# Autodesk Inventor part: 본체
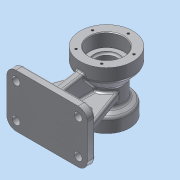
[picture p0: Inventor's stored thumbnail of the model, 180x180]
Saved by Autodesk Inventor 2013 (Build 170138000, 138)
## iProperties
Created: 2015-08
Part Number: 본체
Material: 알루미늄 6061
Document SubType Name: Modeling
Designer: dgall
Density: 2.71 g/cm^3
Mass: 1053.19 g
Surface Area: 752.18 cm^2
Volume: 388.632 cm^3
Author: dgall
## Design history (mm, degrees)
sketch "스케치1"
  geometry: L1 (0, 0)-(0, -80); L2 (0, -80)-(-122, -80); L3 (-122, -80)-(-122, 0); L4 (-122, 0)-(0, 0); L5 (-14, -66)-(-108, -66); L6 (-108, -66)-(-108, -14); L7 (-108, -14)-(-14, -14); L8 (-14, -14)-(-14, -66); C1 r 6 at (-14, -66); C2 r 6 at (-14, -14); C3 r 6 at (-108, -14); C4 r 6 at (-108, -66); 4 further points
  constraints: 16 end point, 4 centre point, 4 coincident, 4 midpoint, 4 parallel, 2 perpendicular, 1 horizontal, 1 horizontal alignment, 1 vertical, 1 vertical alignment
  dimensions: "d0" = 80 distance of L1.start L1.end; "d1" = 122 distance of L1.end L2.end; "d2" = 94 distance of L5.start L5.end; "d3" = 52 distance of L7.end L5.start; "d4" = 12 diameter of C1; "d5" = 12 diameter of C2; "d6" = 12 diameter of C3; "d7" = 12 diameter of C4
extrude "돌출1" new body sketch "스케치1" distance "d8" = 12; taper "d9" = 0 deg
node "작업 평면1"
sketch "스케치2"
  geometry: L1 (80, 12)-(80, 0) reference; L2 (80, 0)-(0, 0) reference; L3 (0, 0)-(0, 12) reference; L4 (0, 12)-(80, 12) reference; L5 (40, 0)-(40, 90); L6 (0, 90)-(90, 90); L7 (0, 90)-(0, 125); L8 (0, 125)-(20, 125); L9 (20, 125)-(25.774, 115); L10 (25.774, 115)-(52.124, 115); L11 (52.124, 115)-(70, 130); L12 (70, 130)-(90, 130); L13 (90, 130)-(90, 90)
  constraints: 18 end point, 5 perpendicular, 2 parallel, 1 midpoint, 1 vertical alignment
  dimensions: "d10" = 90 distance of L5.start L5.end; "d11" = 90 distance of L6.start L6.end; "d12" = 70 diameter of L8 L6; "d13" = 20 distance of L7.end L8.end; "d14" = 60 deg angle of L10 L9; "d15" = 20 distance of L11.end L12.end; "d16" = 40 deg angle of L10 L11; "d17" = 50 diameter of L10 L6; "d18" = 80 diameter of L12 L6; "d19" = 130 distance between parallel lines of L2 L12
revolve "회전1" sketch "스케치2" stored, may be unused: angle "d20" = 90 deg
sketch "스케치3"
  geometry: C1 r 35 at (0, 0) reference; C2 r 20 at (0, 0); 1 further point
  constraints: 1 centre point, 1 coincident
  dimensions: "d21" = 40 diameter of C2
extrude "돌출2" cut sketch "스케치3" distance "d22" = 17; taper "d23" = 0 deg
sketch "스케치4"
  geometry: C1 r 40 at (0, 0) reference; C2 r 26 at (0, 0); 1 further point
  constraints: 1 centre point, 1 coincident
  dimensions: "d24" = 52 diameter of C2
extrude "돌출3" cut sketch "스케치4" distance "d25" = 20; taper "d26" = 0 deg
sketch "스케치5"
  geometry: C1 r 26 at (0, 0) reference; C2 r 19 at (0, 0); 1 further point
  constraints: 1 centre point, 1 coincident
  dimensions: "d27" = 38 diameter of C2
extrude "돌출4" cut sketch "스케치5" distance "d28" = 3; taper "d29" = 0 deg
sketch "스케치6"
  geometry: C1 r 19 at (0, 0) reference; C2 r 16 at (0, 0); 1 further point
  constraints: 1 centre point, 1 coincident
  dimensions: "d30" = 32 diameter of C2
extrude "돌출5" cut sketch "스케치6" stored distance "d31" = 3; taper "d32" = 0 deg
sketch "스케치7" dims "d33" = 66
  geometry: C1 r 26 at (0, 0) reference; C2 r 40 at (0, 0) reference; 3 further points
  constraints: 2 vertical alignment, 1 coincident, 2 other
hole "구멍1" sketch "스케치7" at (0, 33) diameter "d34" = 3.459; stored, may be unused: countersink angle "d38" = 90 deg, drill point angle "d40" = 118 deg; dims "d35" = 10, "d36" = 4, "d37" = 2, "d39" = 13
sketch "스케치8" dims "d44" = 54
  geometry: C1 r 20 at (0, 0) reference; C2 r 35 at (0, 0) reference; 3 further points
  constraints: 2 vertical alignment, 1 coincident, 2 other
hole "구멍2" sketch "스케치8" at (0, 27) diameter "d45" = 3.459; stored, may be unused: countersink angle "d49" = 90 deg, drill point angle "d51" = 118 deg; dims "d46" = 10, "d47" = 4, "d48" = 2, "d50" = 13
node "작업 평면2"
sketch "스케치10"
  geometry: L1 (0, 0)-(0, 12) reference; L2 (0, 12)-(122, 12) reference; L3 (122, 12)-(122, 0) reference; L4 (122, 0)-(0, 0) reference; L5 (10, 12)-(36.529, 84.887); L6 (112, 12)-(85.471, 84.887); L7 (10, 12)-(112, 12); L8 (31, 36)-(31, 30); L9 (43, 36)-(43, 30); L10 (61, 90)-(61, 0); L11 (79, 36)-(79, 30); L12 (91, 36)-(91, 30); C1 r 16 at (61, 90) reference; A1 r 25 centre (61, 90) between (36.529, 84.887) and (85.471, 84.887); A2 r 6 centre (37, 30) between (31, 30) and (43, 30); A3 r 6 centre (37, 36) between (43, 36) and (31, 36); A4 r 6 centre (85, 36) between (91, 36) and (79, 36); A5 r 6 centre (85, 30) between (79, 30) and (91, 30); 1 further point
  constraints: 16 end point, 10 point on circle, 6 symmetric about line, 5 centre point, 4 tangent, 2 parallel, 1 coincident, 1 horizontal alignment, 1 midpoint, 1 perpendicular, 1 point on line, 5 other
  dimensions: "d61" = 70 deg angle of L2 L5; "d62" = 12 distance between parallel lines of L9 L8; "d64" = 6 distance of A2.centre A3.centre; "d65" = 18 distance from line of L7 A2.centre; "d66" = 48 distance of A5.centre A2.centre; "d67" = 10 distance of L1.end L5.start
extrude "돌출7" join sketch "스케치10" stored distance "d68" = 12; taper "d69" = 0 deg
sketch "스케치11"
  geometry: L1 (17, 110)-(0, 110) reference; L2 (0, 110)-(0, 115.27) reference; L3 (0, 115.27)-(13, 115.27) reference; L4 (13, 115.27)-(14.039, 117) reference; L5 (14.039, 117)-(13, 118.73) reference; L6 (13, 118.73)-(0, 118.73) reference; L7 (0, 118.73)-(0, 125) reference; L8 (0, 125)-(20, 125) reference; L9 (20, 125)-(25.774, 115) reference; L10 (25.774, 115)-(52.124, 115) reference; L11 (52.124, 115)-(70, 130) reference; L12 (70, 130)-(90, 130) reference; L13 (90, 130)-(90, 124.73) reference; L14 (90, 124.73)-(77, 124.73) reference; L15 (77, 124.73)-(75.961, 123) reference; L16 (75.961, 123)-(77, 121.27) reference; L17 (77, 121.27)-(90, 121.27) reference; L18 (90, 121.27)-(90, 116) reference; L19 (90, 116)-(70, 116) reference; L20 (70, 116)-(70, 109) reference; L21 (70, 109)-(67, 109) reference; L22 (67, 109)-(67, 106) reference; L23 (67, 106)-(17, 106) reference; L24 (17, 106)-(17, 110) reference; L25 (80, 12)-(80, 0) reference; L26 (80, 0)-(0, 0) reference; L27 (0, 0)-(0, 12) reference; L28 (0, 12)-(34, 12) reference; L29 (34, 12)-(34, 65) reference; L30 (34, 65)-(25.774, 65) reference; L31 (25.774, 65)-(20, 55) reference; L32 (20, 55)-(0, 55) reference; L33 (0, 55)-(0, 70) reference; L34 (0, 70)-(17, 70) reference; L35 (17, 70)-(17, 74) reference; L36 (17, 74)-(67, 74) reference; L37 (67, 74)-(67, 71) reference; L38 (67, 71)-(70, 71) reference; L39 (70, 71)-(70, 64) reference; L40 (70, 64)-(90, 64) reference; L41 (90, 64)-(90, 50) reference; L42 (90, 50)-(70, 50) reference; L43 (70, 50)-(52.124, 65) reference; L44 (52.124, 65)-(46, 65) reference; L45 (46, 65)-(46, 12) reference; L46 (46, 12)-(80, 12) reference; L47 (10, 12)-(10, 56.907); L48 (10, 56.907)-(17.814, 56.907); L49 (17.814, 56.907)-(23.432, 66.256); L50 (23.432, 66.256)-(55.304, 66.256); L51 (55.304, 66.256)-(72.187, 52.089); L52 (72.187, 52.089)-(77.069, 52.089); L53 (77.069, 52.089)-(70, 12); L54 (70, 12)-(10, 12)
  constraints: 16 end point, 4 parallel, 2 point on line, 1 collinear, 1 perpendicular
  dimensions: "d71" = 10 distance of L27.end L47.start; "d72" = 10 distance of L25.start L53.end; "d73" = 80 deg angle of L46 L53; "d74" = 72.64067 distance between parallel lines of L14 L52; "d75" = 58.47368 distance between parallel lines of L14 L50; "d76" = 67.82263 distance between parallel lines of L14 L48; "d77" = 15.8008 distance between parallel lines of L15 L49; "d78" = 3.00622 distance between parallel lines of L51 L43
extrude "돌출8" join sketch "스케치11" stored distance "d79" = 12; taper "d80" = 0 deg
fillet "모깎기2" dims "d81" = 5
fillet "모깎기3" dims "d82" = 0.3
fillet "모깎기4" dims "d83" = 3
fillet "모깎기5" dims "d84" = 14
sketch "스케치12"
  geometry: L1 (10, 52.119)-(10, 15) reference; L2 (3, 12)-(14, 12) reference; 3 further points
  constraints: 1 other
  dimensions: "d85" = 16 distance from line of L1 point (26, 36); "d86" = 24 distance from line of L2 point (26, 36)
feature "엠보싱1" sketch "스케치12" dims "d0" = 80, "d1" = 122, "d2" = 94, "d3" = 52, "d4" = 12, "d5" = 12, "d6" = 12, "d7" = 12, "d10" = 90, "d11" = 90, "d12" = 70, "d13" = 20, "d14" = 60 deg, "d15" = 20, "d16" = 40 deg, "d17" = 50, "d18" = 80, "d19" = 130, "d87" = 0.5, "d88" = 0
chamfer "모따기1" distance "d89" = 1; stored, may be unused: second distance "d90" = 2, angle "d91" = 45 deg
chamfer "모따기2" distance "d92" = 1; stored, may be unused: second distance "d93" = 2, angle "d94" = 45 deg
node "솔리드1"
pattern_circular "원형 패턴1" dims angle "d42" = 360 deg
pattern_circular "원형 패턴3" dims angle "d96" = 360 deg
node "절단 모서리 투영1"
node "절단 모서리 투영3"
node "절단 모서리 투영4"
